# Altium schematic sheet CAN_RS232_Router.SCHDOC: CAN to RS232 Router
size C; Organization: Altium Limited; Address1: L3, 12a Rodborough Rd; Address2: Frenchs Forest; Address3: NSW; Address4: Australia 2086; DocumentNumber: 1; SheetNumber: 1; SheetTotal: 2
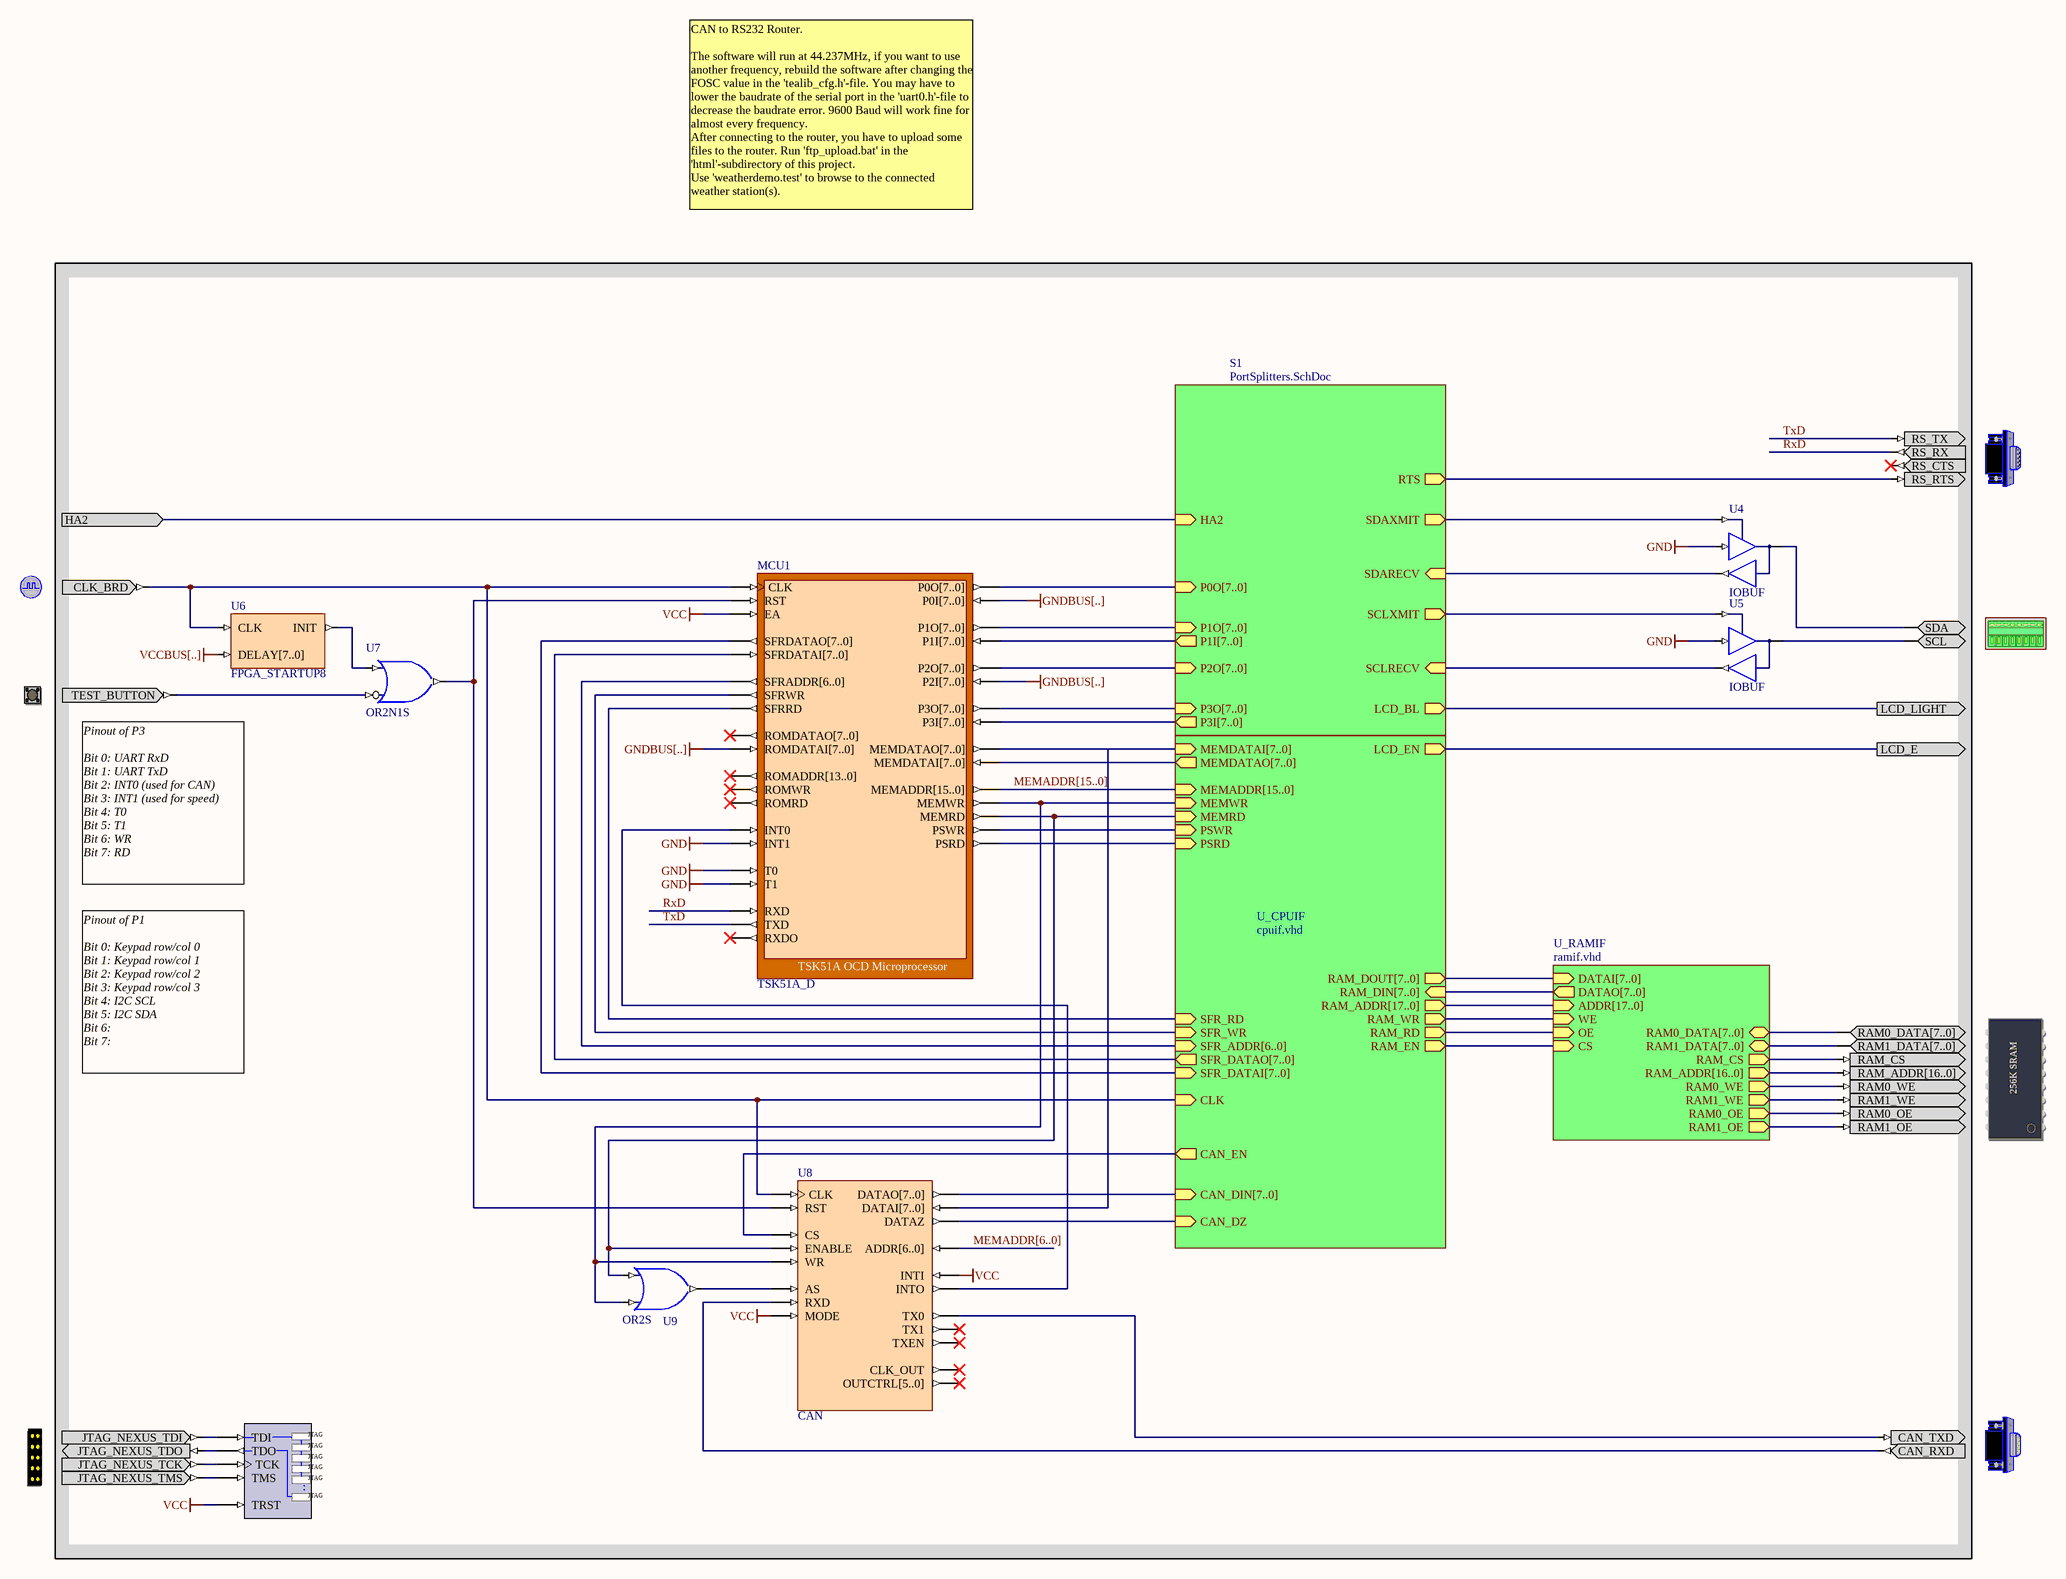
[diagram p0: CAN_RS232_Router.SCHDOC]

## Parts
(Parts that share a designator on the sheet are numbered #1, #2 ... from top to bottom, then left to right.)
?#1  RS232CNTR  (value not drawn)
?#2  CLOCK_BOARD  (value not drawn)
?#3  ADCDAC_I2C  (value not drawn)
?#4  TEST_BUTTON  (value not drawn)
?#5  MEMORY256KX8  (value not drawn)
?#6  CANCNTR  (value not drawn)
?#7  NEXUS_JTAG_CONNECTOR  (value not drawn)
MCU1  TSK51A_D
NEXUS_JTAG_PORT  NEXUS_JTAG_PORT  (value not drawn)
U4  IOBUF
U5  IOBUF
U6  FPGA_STARTUP8
U7  OR2N1S
U8  CAN
U9  OR2S

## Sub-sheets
S1 = PortSplitters.SchDoc: P0O[7..0] (in), P1O[7..0] (in), P1I[7..0] (out), P2O[7..0] (in), P3O[7..0] (in), P3I[7..0] (out), HA2 (in), SCLXMIT (out), LCD_BL (out), RTS (out), SDAXMIT (out), SCLRECV (in), SDARECV (in)
U_CPUIF = cpuif.vhd: MEMWR (in), RAM_EN (out), RAM_WR (out), RAM_RD (out), RAM_DOUT[7..0] (out), MEMRD (in), LCD_EN (out), RAM_ADDR[17..0] (out), CLK (in), SFR_ADDR[6..0] (in), SFR_DATAI[7..0] (in), SFR_DATAO[7..0] (out), SFR_WR (in), SFR_RD (in), RAM_DIN[7..0] (in), PSWR (in), PSRD (in), MEMADDR[15..0] (in), MEMDATAI[7..0] (in), MEMDATAO[7..0] (out), CAN_EN (out), CAN_DIN[7..0] (in), CAN_DZ (in)
U_RAMIF = ramif.vhd: DATAI[7..0] (in), DATAO[7..0] (out), ADDR[17..0] (in), WE (in), OE (in), CS (in), RAM0_DATA[7..0] (bidir), RAM1_DATA[7..0] (bidir), RAM_ADDR[16..0] (out), RAM0_WE (out), RAM1_WE (out), RAM0_OE (out), RAM1_OE (out), RAM_CS (out)

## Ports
HA2 (in), LCD_E (out), LCD_LIGHT (out)

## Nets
GND: MCU1.INT1 MCU1.T0 MCU1.T1 U4.I U5.I
VCC: MCU1.EA NEXUS_JTAG_PORT.TRST U8.INTI U8.MODE
VCCBUS[..]: U6.DELAY[7..0]
HA2: port HA2, sheet S1/HA2
LCD_E: port LCD_E, sheet U_CPUIF/LCD_EN
LCD_LIGHT: port LCD_LIGHT, sheet S1/LCD_BL
RxD: ?#1.RS_RX MCU1.RXD
TxD: ?#1.RS_TX MCU1.TXD
Net?#1_RS_RTS: ?#1.RS_RTS ; sheet S1/RTS
Net?#2_CLK_BRD: ?#2.CLK_BRD MCU1.CLK U6.CLK U8.CLK ; sheet U_CPUIF/CLK
Net?#3_SCL: ?#3.SCL U5.IO
Net?#3_SDA: ?#3.SDA U4.IO
Net?#4_TEST_BUTTON: ?#4.TEST_BUTTON U7.I0
Net?#5_RAM0_OE: ?#5.RAM0_OE ; sheet U_RAMIF/RAM0_OE
Net?#5_RAM0_WE: ?#5.RAM0_WE ; sheet U_RAMIF/RAM0_WE
Net?#5_RAM1_OE: ?#5.RAM1_OE ; sheet U_RAMIF/RAM1_OE
Net?#5_RAM1_WE: ?#5.RAM1_WE ; sheet U_RAMIF/RAM1_WE
Net?#5_RAM_CS: ?#5.RAM_CS ; sheet U_RAMIF/RAM_CS
Net?#6_CAN_RXD: ?#6.CAN_RXD U8.RXD
Net?#6_CAN_TXD: ?#6.CAN_TXD U8.TX0
Net?#7_JTAG_NEXUS_TCK: ?#7.JTAG_NEXUS_TCK NEXUS_JTAG_PORT.TCK
Net?#7_JTAG_NEXUS_TDI: ?#7.JTAG_NEXUS_TDI NEXUS_JTAG_PORT.TDI
Net?#7_JTAG_NEXUS_TDO: ?#7.JTAG_NEXUS_TDO NEXUS_JTAG_PORT.TDO
Net?#7_JTAG_NEXUS_TMS: ?#7.JTAG_NEXUS_TMS NEXUS_JTAG_PORT.TMS
NetMCU1_INT0: MCU1.INT0 U8.INTO
NetMCU1_MEMRD: MCU1.MEMRD U8.ENABLE U9.I0 ; sheet U_CPUIF/MEMRD
NetMCU1_MEMWR: MCU1.MEMWR U8.WR U9.I1 ; sheet U_CPUIF/MEMWR
NetMCU1_PSRD: MCU1.PSRD ; sheet U_CPUIF/PSRD
NetMCU1_PSWR: MCU1.PSWR ; sheet U_CPUIF/PSWR
NetMCU1_RST: MCU1.RST U7.O U8.RST
NetMCU1_SFRRD: MCU1.SFRRD ; sheet U_CPUIF/SFR_RD
NetMCU1_SFRWR: MCU1.SFRWR ; sheet U_CPUIF/SFR_WR
NetU4_O: U4.O ; sheet S1/SDARECV
NetU4_T: U4.T ; sheet S1/SDAXMIT
NetU5_O: U5.O ; sheet S1/SCLRECV
NetU5_T: U5.T ; sheet S1/SCLXMIT
NetU6_INIT: U6.INIT U7.I1
NetU8_AS: U8.AS U9.O
NetU8_CS: U8.CS ; sheet U_CPUIF/CAN_EN
NetU8_DATAZ: U8.DATAZ ; sheet U_CPUIF/CAN_DZ
(unnamed): sheet U_CPUIF/RAM_EN, sheet U_RAMIF/CS
(unnamed): sheet U_CPUIF/RAM_WR, sheet U_RAMIF/WE  [a separate net that carries the same name]
(unnamed): sheet U_CPUIF/RAM_RD, sheet U_RAMIF/OE  [a separate net that carries the same name]

Not connected (* = marked no-connect by the designer): ?#1 RS_CTS*; ?#5 RAM0_DATA[7..0] RAM1_DATA[7..0] RAM_ADDR[16..0]; MCU1 MEMADDR[15..0] MEMDATAI[7..0] MEMDATAO[7..0] P0I[7..0] P0O[7..0] P1I[7..0] P1O[7..0] P2I[7..0] P2O[7..0] P3I[7..0] P3O[7..0] ROMADDR[13..0]* ROMDATAI[7..0] ROMDATAO[7..0]* ROMRD* ROMWR* RXDO* SFRADDR[6..0] SFRDATAI[7..0] SFRDATAO[7..0]; U8 ADDR[6..0] CLK_OUT* DATAI[7..0] DATAO[7..0] OUTCTRL[5..0]* TX1* TXEN*

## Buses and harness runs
bus MEMADDR[6..0]
bus MEMADDR[15..0] = sheet U_CPUIF/MEMADDR[15..0]
bus sheet U_CPUIF/RAM_ADDR[17..0] = sheet U_RAMIF/ADDR[17..0]
bus sheet U_CPUIF/RAM_DIN[7..0] = sheet U_RAMIF/DATAO[7..0]
bus sheet U_CPUIF/RAM_DOUT[7..0] = sheet U_RAMIF/DATAI[7..0]

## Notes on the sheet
- CAN to RS232 Router.
  The software will run at 44.237MHz, if you want to use another frequency, rebuild the software after changing the FOSC value in the 'tealib_cfg.h'-file. You may have to lower the baudrate of the serial port in the 'uart0.h'-file to decrease the baudrate error. 9600 Baud will work fine for almost every frequency.
  After connecting to the router, you have to upload some files to the router. Run 'ftp_upload.bat' in the 'html'-subdirectory of this project.
  Use 'weatherdemo.test' to browse to the connected weather station(s).
- Pinout of P3
  Bit 0: UART RxD
  Bit 1: UART TxD
  Bit 2: INT0 (used for CAN)
  Bit 3: INT1 (used for speed)
  Bit 4: T0
  Bit 5: T1
  Bit 6: WR
  Bit 7: RD
- Pinout of P1
  Bit 0: Keypad row/col 0
  Bit 1: Keypad row/col 1
  Bit 2: Keypad row/col 2
  Bit 3: Keypad row/col 3
  Bit 4: I2C SCL
  Bit 5: I2C SDA
  Bit 6:
  Bit 7:
- Labels drawn without touching a wire or pin: GNDBUS[..]

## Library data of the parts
?#1 = RS232CNTR: DCE Serial Port Connector; PortComponent: True
?#2 = CLOCK_BOARD: Global System Clock Supply; PortComponent: True
?#3 = ADCDAC_I2C: Analog Digital/ Digital Analog Converter, I2C Interface; PortComponent: True
?#4 = TEST_BUTTON: Test Button; PortComponent: True
?#5 = MEMORY256KX8: SRAM 256kx8; PortComponent: True
?#6 = CANCNTR: CAN Bus Connector; PortComponent: True
?#7 = NEXUS_JTAG_CONNECTOR: JTAG Port; PortComponent: True
MCU1 = TSK51A_D: TSK51A OCD Microprocessor; NEXUS_CORE: Processor_OCDS; NEXUS_JTAG_DEVICE: True; NEXUS_JTAG_ORDER: 0; ChildModel1: RAM256x8_TSK51D
NEXUS_JTAG_PORT = NEXUS_JTAG_PORT: Nexus Processor JTAG Chain Connector; NEXUS_JTAG_CONNECTOR: True
U4 U5 = IOBUF: Input/Output Buffer; ArchiveName: GENERIC
U6 = FPGA_STARTUP8: FPGA Startup With 8 Bit Delay
U7 = OR2N1S: 2-Input OR Gate with Active Low A Input, Single Pin Version; Xilinx Equivalent: OR2B1; ArchiveName: GENERIC
U8 = CAN: CAN Controller; ChildModel1: CAN10000_DRAM8X64
U9 = OR2S: 2-Input OR Gate, Single Pin Version; Xilinx Equivalent: OR2; ArchiveName: GENERIC; VHDLIB_SIM: GENERIC_LIB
